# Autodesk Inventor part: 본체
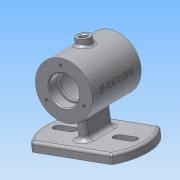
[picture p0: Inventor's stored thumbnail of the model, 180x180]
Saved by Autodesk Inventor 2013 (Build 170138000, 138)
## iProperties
Created: 2017-12
Part Number: 본체
Material: 알루미늄 6061
Document SubType Name: Modeling
Designer: Administrator
Density: 2.71 g/cm^3
Mass: 467.724 g
Surface Area: 486.557 cm^2
Volume: 172.592 cm^3
Author: Administrator
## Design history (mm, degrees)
sketch "스케치1"
  geometry: L1 (-35, -42.426)-(-35, 42.426); L2 (35, -42.426)-(35, 42.426); L3 (0, 0)-(0, 71.634); L4 (5, -40)-(5, -24); L5 (-5, -40)-(-5, -24); L6 (-1.738, 0)-(67.006, 0); L7 (5, 40)-(5, 24); L8 (-5, 40)-(-5, 24); L9 (-15, -5)-(15, -5); L10 (-15, 5)-(15, 5); A1 r 55 centre (0, 0) between (-35, -42.426) and (35, -42.426); A2 r 55 centre (0, 0) between (35, 42.426) and (-35, 42.426); A3 r 5 centre (0, -40) between (-5, -40) and (5, -40); A4 r 5 centre (0, -24) between (5, -24) and (-5, -24); A5 r 5 centre (0, 40) between (5, 40) and (-5, 40); A6 r 5 centre (0, 24) between (-5, 24) and (5, 24); A7 r 5 centre (-15, 0) between (-15, 5) and (-15, -5); A8 r 5 centre (15, 0) between (15, -5) and (15, 5); 1 further point
  constraints: 20 end point, 16 point on circle, 8 centre point, 7 symmetric about line, 4 parallel, 4 tangent, 2 coincident, 2 perpendicular, 1 point on line, 1 vertical, 3 other
  dimensions: "d2" = 70 distance between parallel lines of L2 L1; "d3" = 0 horizontal distance of A4.centre A3.centre; "d4" = 10 diameter of A3; "d5" = 10 diameter of A4; "d6" = 24 distance of point (0, 0) A4.centre; "d7" = 16 distance of A4.centre A3.centre; "d8" = 0 vertical distance of point (0, 0) A7.centre; "d9" = 10 diameter of A7; "d10" = 10 diameter of A8; "d11" = 30 distance of A7.centre A8.centre
extrude "돌출1" new body sketch "스케치1" distance "d12" = 10; taper "d13" = 0 deg
extrude "돌출2" join sketch "스케치1" distance "d14" = 50; taper "d15" = 0 deg
node "스케치2"
sketch "스케치3"
  geometry: L1 (-35, 42.426)-(-35, -42.426) reference; L2 (-5, 40)-(-5, 24); L3 (5, 40)-(5, 24); L4 (0, 0)-(50.574, 0); L5 (-5, -40)-(-5, -24); L6 (5, -40)-(5, -24); A1 r 55 centre (0, 0) between (-35, -42.426) and (35, -42.426) reference; A2 r 5 centre (0, 40) between (5, 40) and (-5, 40) reference; A3 r 5 centre (0, 40) between (5, 40) and (-5, 40); A4 r 5 centre (0, 24) between (-5, 24) and (5, 24); A5 r 5 centre (0, -40) between (-5, -40) and (5, -40); A6 r 5 centre (0, -40) between (-5, -40) and (5, -40); A7 r 5 centre (0, -24) between (5, -24) and (-5, -24)
  constraints: 10 end point, 10 point on circle, 9 symmetric about line, 5 centre point, 2 coincident, 2 parallel, 2 tangent, 1 perpendicular, 3 other
  dimensions: "d16" = 10 diameter of A3; "d18" = 10 diameter of A4; "d19" = 16 distance of A4.centre A3.centre
extrude "돌출3" cut sketch "스케치3" distance "d20" = 50; taper "d21" = 0 deg
sketch "스케치4"
  geometry: L1 (0, -24)-(0, -19) reference; C1 r 30 at (62, 0); 1 further point
  constraints: 1 centre point
  dimensions: "d22" = 0 vertical distance of point (0, 0) C1.centre; "d23" = 60 diameter of C1; "d24" = 62 distance from line of L1 C1.centre
extrude "돌출4" join sketch "스케치4" stored distance "d25" = 70; taper "d26" = 0 deg
sketch "스케치5"
  geometry: C1 r 30 at (0, 0) reference; C2 r 16 at (0, 0); 1 further point
  constraints: 1 centre point, 1 coincident
  dimensions: "d27" = 32 diameter of C2
extrude "돌출5" cut sketch "스케치5" distance "d29" = 12; taper "d30" = 0 deg
sketch "스케치6"
  geometry: C1 r 16 at (0, 0) reference; C2 r 14 at (0, 0); 1 further point
  constraints: 1 centre point, 1 coincident
  dimensions: "d31" = 28 diameter of C2
extrude "돌출6" cut sketch "스케치6" distance "d33" = 3; taper "d34" = 0 deg
hole "구멍1" diameter "d39" = 50; stored, may be unused: countersink angle "d43" = 90 deg, drill point angle "d45" = 0 deg; dims "d37" = 10, "d38" = 10, "d40" = 6, "d41" = 4, "d42" = 2, "d44" = 40
node "작업 평면1"
sketch "스케치8"
  geometry: C1 r 8 at (0, 0); C2 r 4 at (0, 0); 1 further point
  constraints: 2 centre point, 2 coincident
  dimensions: "d47" = 8 diameter of C2; "d49" = 16 diameter of C1
extrude "돌출7" join sketch "스케치8" stored distance "d50" = 40; taper "d51" = 0 deg
extrude "돌출8" cut sketch "스케치8" stored distance "d52" = 40; taper "d53" = 0 deg
sketch "스케치9" dims "d54" = 46
  geometry: C1 r 16 at (0, 0) reference; 3 further points
  constraints: 1 coincident, 1 vertical alignment, 2 other
hole "구멍2" sketch "스케치9" at (0, 23) diameter "d57" = 3.242; stored, may be unused: countersink angle "d61" = 90 deg, drill point angle "d63" = 120 deg; dims "d58" = 8, "d59" = 4, "d60" = 2, "d62" = 10
node "작업 평면2"
sketch "스케치10"
  geometry: L1 (-35, 92)-(-35, 32) reference; 2 further points
  constraints: 1 other
  dimensions: "d68" = 35 distance from line of L1 point (0, 62); "d69" = 30 vertical distance of L1.start point (0, 62)
feature "엠보싱1" sketch "스케치10" dims "d70" = 0.5, "d71" = 0
fillet "모깎기1" dims "d72" = 5
fillet "모깎기2" dims "d73" = 3
chamfer "모따기1" distance "d74" = 1; stored, may be unused: second distance "d75" = 2, angle "d76" = 45 deg
fillet "모깎기3" dims "d77" = 3
fillet "모깎기4" dims "d78" = 0.3
fillet "모깎기5" dims "d79" = 3
fillet "모깎기6" dims "d82" = 3
node "솔리드1"
mirror "대칭1"
mirror "대칭2"
pattern_circular "원형 패턴1" dims angle "d65" = 360 deg
mirror "대칭3"
other parameters: "d46" = -99, "d67" = 61
